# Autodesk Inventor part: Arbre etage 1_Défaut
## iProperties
Shininess: 64.0
Length Units: 11269
Angle Units: 11279
Time Units: 11290
Mass Units: 11283
Length Display Precision: 3
Angle Display Precision: 2
Compacted: True
Part Number: Arbre etage 1_Défaut
Document SubType Name: Modeling
Created: 2006-01
Material: Par défaut
Designer: Fricot
Density: 0.0
Volumn: 0.0
Area: 0.0
PropertySet Name: Model Information
Control State: 0
Master: False
Checked Out: False
Author: Fricot
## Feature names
1. Base1
